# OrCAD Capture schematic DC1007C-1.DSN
size Custom; title: High Efficiency Battery Charger / USB Power Manager; rev: 1; note: DEMO CIRCUIT 1007C
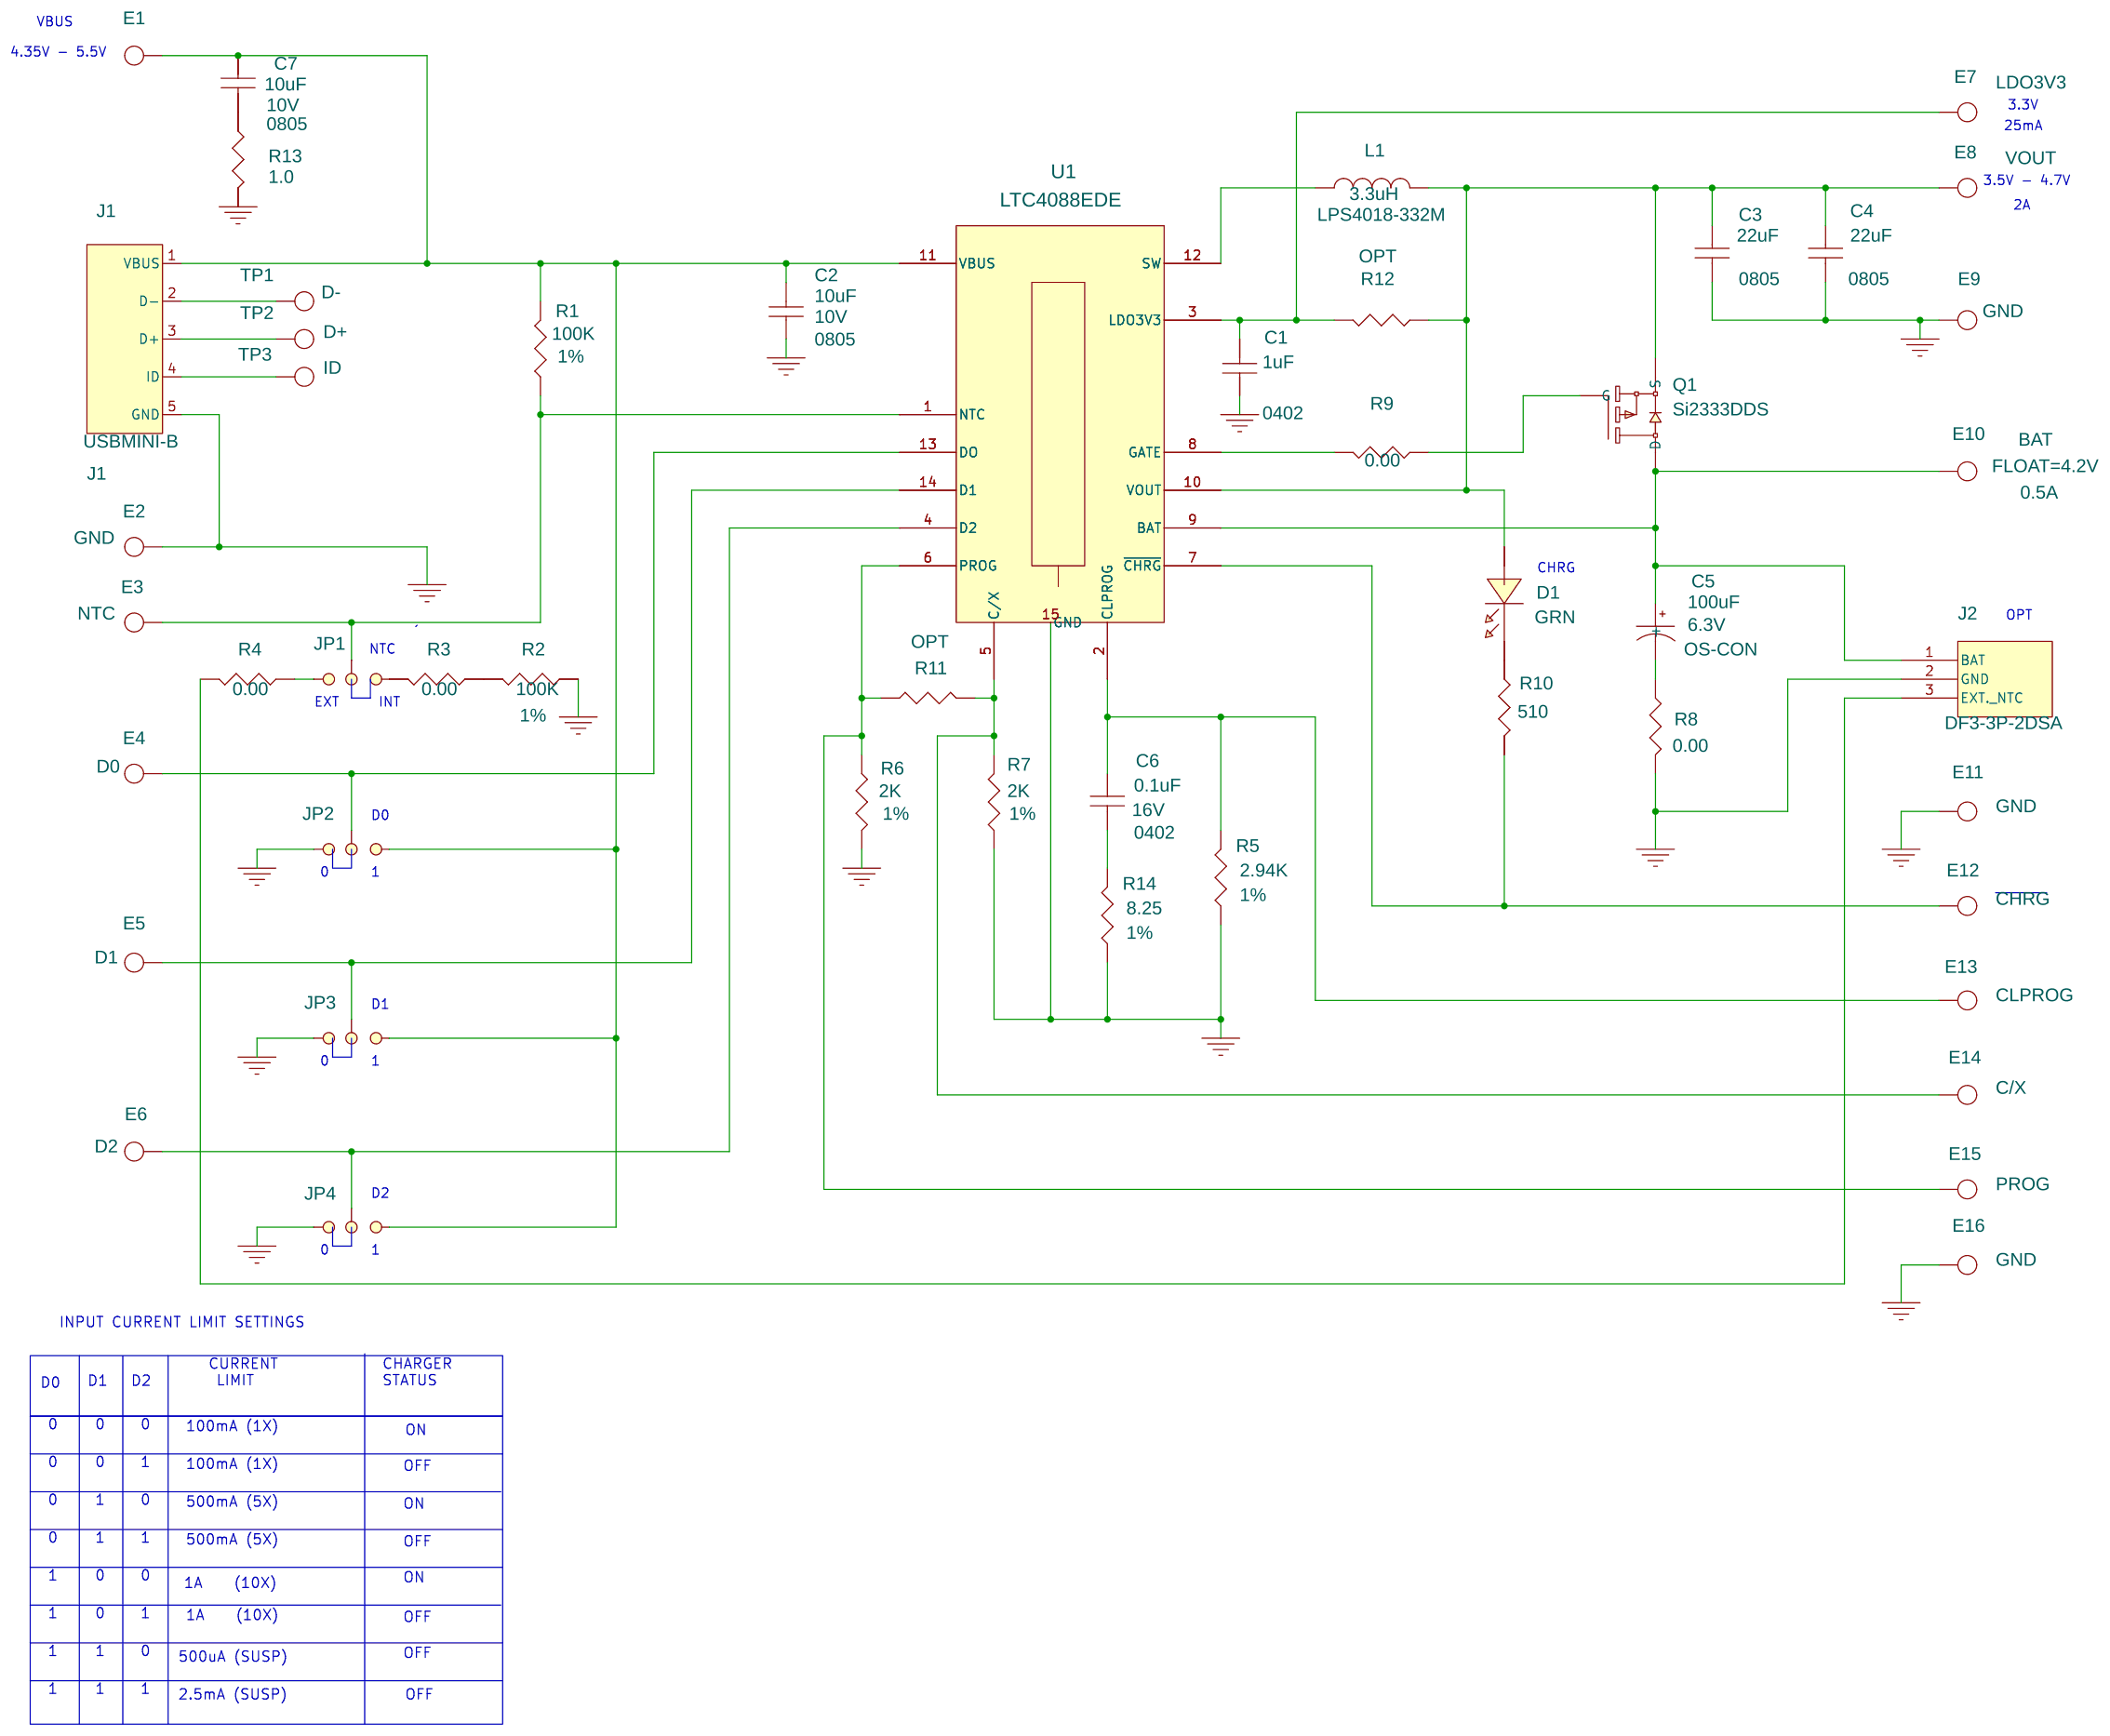
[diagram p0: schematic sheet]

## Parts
C1  1uF  [0402-SMALL]
C2  10uF  [0805]
C3  22uF  [0805]
C4  22uF  [0805]
C5  100uF  [OSCON-B6]
C6  0.1uF  [0402-SMALL]
C7  10uF  [0805]
D1  GRN  [LED-WURTH-150060GS75000]
E1  WALL  [MILLMAX-2501-2]
E2  GND  [MILLMAX-2501-2]
E3  NTC  [MILL-MAX-2308]
E4  D0  [MILL-MAX-2308]
E5  D1  [MILL-MAX-2308]
E6  D2  [MILL-MAX-2308]
E7  LDO3V3  [MILL-MAX-2308]
E8  VOUT  [MILLMAX-2501-2]
E9  GND  [MILLMAX-2501-2]
E10  BAT  [MILLMAX-2501-2]
E11  GND  [MILLMAX-2501-2]
E12  CHRG  [MILL-MAX-2308]
E13  CLPROG  [MILL-MAX-2308]
E14  C/X  [MILL-MAX-2308]
E15  PROG  [MILL-MAX-2308]
E16  GND  [MILL-MAX-2308]
J1  USBMINI-B  [TYCO-440247]
J2  DF3-3P-2DSA  [DF32DSHEADER]
JP1  JP3X1/079\NO  [2MMJUMP3]
JP2  JP3X1/079\NO  [2MMJUMP3]
JP3  JP3X1/079\NO  [2MMJUMP3]
JP4  JP3X1/079\NO  [2MMJUMP3]
L1  3.3uH  [LPS4018]
Q1  12V  [Si2333DS]
R1  100K  [0402-SMALL]
R2  100K  [0402-SMALL]
R3  0.00  [0402-SMALL]
R4  0.00  [0402-SMALL]
R5  2.94K  [0402-SMALL]
R6  2K  [0402-SMALL]
R7  2K  [0402-SMALL]
R8  0.00  [0402-SMALL]
R9  0.00  [0402-SMALL]
R10  510  [0402-SMALL]
R11  OPT  [0402-SMALL]
R12  OPT  [0402-SMALL]
R13  1.0  [0402-SMALL]
R14  8.25  [0402-SMALL]
TP1  TESTPOINT  [TP\KEY\1502-2A]
TP2  TESTPOINT  [TP\KEY\1502-2A]
TP3  TESTPOINT  [TP\KEY\1502-2A]
U1  LTC4088-1  [DE14DFN4X3]

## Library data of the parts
C1 = C1608X5R0J475M: 2nd Part Field: 0402; 5th Part Field: C1608X5R0J225M
C2 C7 = CAP_NP: CAP, 0805 10uF 20% 10V X5R; Part Number: MUR GRM21BR61A106KE19; VOLT: 10V
C3 C4 = C2012X5R0J156M: 5th Part Field: C2012X5R0J226M
C5 = OSCON-B6: PART FIELD: 6.3V; PART FIELD 2: OS-CON
C6 = C1608X5R0J475M: 1st Part Field: 16V; 2nd Part Field: 0402; 3rd Part Field: X7R; 4th Part Field: MURATA; 5th Part Field: GRM155R71C104KA88
D1 = ln1351-c-tr_1: 5th Part Field: 150060GS75000; 9th Part Field: CHGR
E1 E2 E7-E9 E11 E16 = TP_KEY_1502-2: TURRET; Part Number: MILL-MAX 2501-2
E3-E6 = TP_KEY_1502-2: TURRET; Part Number: MILL-MAX 2308-2
E10 = TP_KEY_1502-2: TURRET; Part Number: MILL-MAX 2501-2; TEXT 2: 0.5A; Text 1: FLOAT=4.2V
E12 E13 = TP_KEY_1502-2: TURRET; Part Number: TP\MMX\2308
E14 E15 = TP_KEY_1502-2: TURRET; Part Number: TP\MMX\2308-2
J1 = USB_MINI-B_0
J2 = CON3_3
JP1-JP4 = JP3X1_079_NO_0: HEADER,3 PINS 2mm; Part Number: COMM 2802S-03G2
L1 = CR75-100MC: 4th Part Field: Coilcraft; 5th Part Field: LPS4018-332M
Q1 = Si2333DS_1: 5th Part Field: Si2333DDS
R1 R2 = CR16-103JM_0: RES, 0402 100K OHMS 1% 1/10W; 2nd Part Field: 1%; 5th Part Field: CR16-1153JM; Part Number: VISHAY CRCW0402 100K 1%; Tolerance: 1%
R3 R4 R9 R12 = CR16-103JM_0: RES, 0402 0.00 OHMS 1% 1/10W; 2nd Part Field: 1%; 5th Part Field: CR16-1153JM; Part Number: VISHAY CRCW0402 0.00 1%; Tolerance: 1%
R5 = CR16-103JM_0: RES, 0402 2.94K OHMS 1% 1/10W; 2nd Part Field: 1%; 5th Part Field: CR16-2111JM; Part Number: VISHAY CRCW0402 2.94K 1%; Tolerance: 1%
R6 R7 = CR16-103JM_0: RES, 0402 1K OHMS 1% 1/10W; 2nd Part Field: 1%; 5th Part Field: CR16-102JM; Part Number: VISHAY CRCW0402 1K 1%; Tolerance: 1%
R8 = CR05-1R0JM: 5th Part Field: CR05-0R0JM
R10 = CR16-103JM_0: RES, 0402 510 OHMS 5% 1/16W; 2nd Part Field: 1%; 5th Part Field: CR16-5100JM; Part Number: AAC CR05-511JM
R11 = RESISTOR
R13 = CR16-103JM_0: RES, 0402 1.0 OHMS 1% 1/10W; 2nd Part Field: 1%; 5th Part Field: CR16-2111JM; Part Number: VISHAY CRCW0402 1R00 1%; Tolerance: 1%
R14 = CR16-103JM_0: RES, 0402 8.25 OHMS 1% 1/10W; 2nd Part Field: 1%; 5th Part Field: CR16-2111JM; Part Number: VISHAY CRCW0402 8R25 1%; Tolerance: 1%
TP1 = TP_KEY_1502-2: 7th Part Field: TEST POINT; 9th Part Field: D-
TP2 = TP_KEY_1502-2: 7th Part Field: TEST POINT; 9th Part Field: D+
TP3 = TP_KEY_1502-2: 7th Part Field: TEST POINT; 9th Part Field: ID
U1 = LTC4089edjc_10: 5th Part Field: LTC4088EDE

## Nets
GND: C1.1 C2.1 C3.2 C4.2 E2.1 E9.1 E11.1 E16.1 J1.5(GND) J2.2(GND) JP2.1 JP3.1 JP4.1 R2.2 R5.2 R6.1 R7.2 R8.2 R13.1 R14.2 U1.15(GND)
N16559543: E4.1 JP2.2 U1.13(DO)
N16739334: C2.2 C7.1 E1.1 J1.1(VBUS) JP2.3 JP3.3 JP4.3 R1.1 U1.11(VBUS)
N16740587: E5.1 JP3.2 U1.14(D1)
N16740774: E6.1 JP4.2 U1.4(D2)
N16743199: E14.1 R7.1 R11.2 U1.5(C/X)
N16744337: E3.1 JP1.2 R1.2 U1.1(NTC)
N16747629: C3.1 C4.1 D1.2(A) E8.1 L1.2 Q1.2(S) R12.2 U1.10(VOUT)
N16751190: E15.1 R6.2 R11.1 U1.6(PROG)
N16752733: C5.1(+) E10.1 J2.1(BAT) Q1.3(D) U1.9(BAT)
N16755835: Q1.1(G) R9.2
N16774080: J2.3(EXT._NTC) R4.1
N16779487: E12.1 R10.1 U1.7(~{CHRG})
N16779701: J1.2(D-) TP1.1
N16779735: J1.3(D+) TP2.1
N16780009: J1.4(ID) TP3.1
N16780114: JP1.1 R4.2
N16784483: C1.2 E7.1 R12.1 U1.3(LDO3V3)
N16788355: R9.1 U1.8(GATE)
N16788460: C5.2(-) R8.1
N16799859: C6.2 R14.1
N16813156: C6.1 E13.1 R5.1 U1.2(CLPROG)
N16814611: R2.1 R3.2
N16814612: JP1.3 R3.1
N16814891: D1.1(K) R10.2
N16815930: C7.2 R13.2
N16870476: L1.1 U1.12(SW)

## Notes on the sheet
- VBUS
- 4.35V - 5.5V
- 3.3V
- 25mA
- 3.5V - 4.7V
- 2A
- CHRG
- OPT
- NTC
- EXT
- INT
- D0
- 0
- 1
- D1
- 0
- 1
- D2
- 0
- 1
- INPUT CURRENT LIMIT SETTINGS
- CURRENT
   LIMIT
- CHARGER
  STATUS
- D0
- D1
- D2
- 0
- 0
- 0
- 100mA (1X)
- ON
- 0
- 0
- 1
- 100mA (1X)
- OFF
- 0
- 1
- 0
- 500mA (5X)
- ON
- 0
- 1
- 1
- 500mA (5X)
- OFF
- 1
- 0
- 0
- 1A    (10X)
- ON
- 1
- 0
- 1
- 1A    (10X)
- OFF
- 1
- 1
- 0
- 500uA (SUSP)
- OFF
- 1
- 1
- 1
- 2.5mA (SUSP)
- OFF
